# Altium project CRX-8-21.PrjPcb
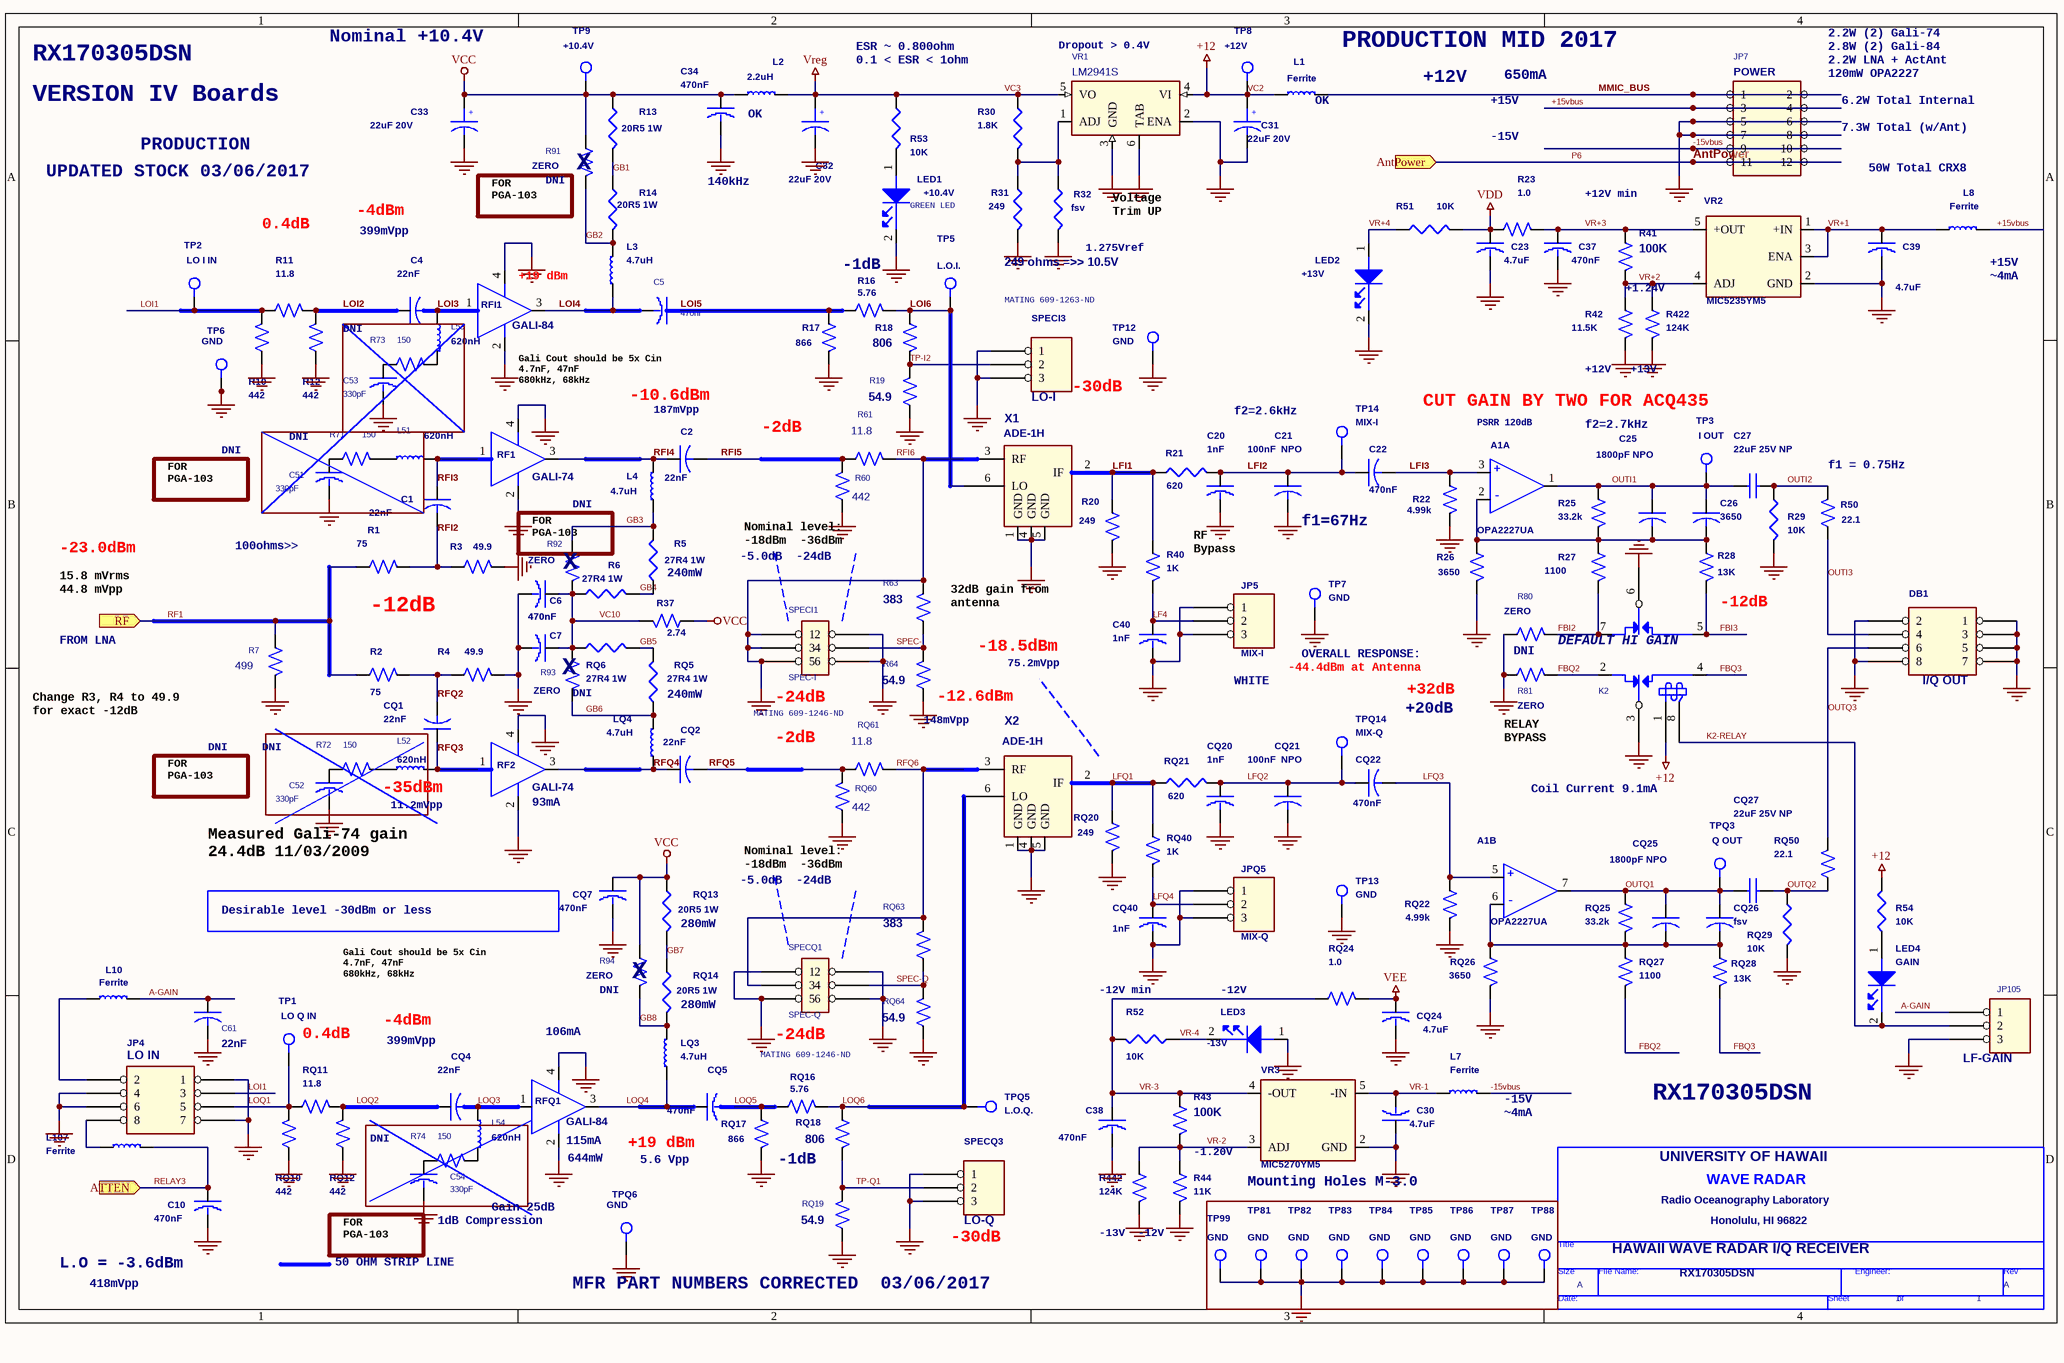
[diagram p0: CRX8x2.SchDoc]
3 sheets, 264 parts. Net scope: flat (ports and power ports of the same name join across sheets).
Board file: CRX-8-21.PcbDoc
Sheets:
  CRX8x2.SchDoc
  LNA.SchDoc
  CHANGE LOG.SchDoc

## Sheet CRX8x2.SchDoc
size 386 x 246 mm; Organization: Altium Limited; Address1: L3, 12a Rodborough Rd; Address2: Frenchs Forest; Address3: NSW; Address4: Australia 2086

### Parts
(Parts that share a designator on the sheet are numbered #1, #2 ... from top to bottom, then left to right.)
*#1  Doc: RX170305DSN  RevCode: A  Title: HAWAII WAVE RADAR I/Q RECEIVER  OrgName: UNIVERSITY OF HAWAII  OrgAddr1: Radio Oceanography Laboratory  OrgAddr3: Honolulu, HI 96822  Page Number: 1  (hidden comment: HWRadar)  (graphical)
A1  OPA2227UA  [DIP8]  (parts A,B of 2)
C1  22nF  [C1206]
C2  22nF  [C1206]
C4  22nF  [C1206]
C5  470nF  [C1206]
C6  470nF  [C1206]
C7  470nF  [C1206]
C10  470nF  [C1206]
C20  1nF  [C1206]
C21  100nF  NPO  [C1206]
C22  470nF  [BFC2_416]
C23  4.7uF  [C1206]
C25  1800pF NPO  [C1206]
C26  3650  [C1206]
C27  22uF 25V NP  [2220]
C30  4.7uF  [C1206]
C31  22uF 20V  [C2917]
C32  22uF 20V  [C2917]
C33  22uF 20V  [C2917]
C34  470nF  [C1206]
C37  470nF  [C1206]
C38  470nF  [C1206]
C39  4.7uF  [C1206]
C40  1nF  [C1206]
C51  330pF  [C1206]
C52  330pF  [C1206]
C53  330pF  [C1206]
C54  330pF  [C1206]
C61  22nF  [C1206]
CQ1  22nF  [C1206]
CQ2  22nF  [C1206]
CQ4  22nF  [C1206]
CQ5  470nF  [C1206]
CQ7  470nF  [C1206]
CQ20  1nF  [C1206]
CQ21  100nF  NPO  [C1206]
CQ22  470nF  [BFC2_416]
CQ24  4.7uF  [C1206]
CQ25  1800pF NPO  [C1206]
CQ26  fsv  [C1206]
CQ27  22uF 25V NP  [2220]
CQ40  1nF  [C1206]
DB1  I/Q OUT  [TSW-4X2M]
JP4  LO IN  [TSW-4X2M]
JP5  MIX-I  [SIP3]
JP7  POWER  [TSW-6X2M]
JP105  LF-GAIN  [SIP3]
JPQ5  MIX-Q  [SIP3]
K2  G6K-2F-RF-S DC12  [RELAY-RF]  (value not drawn)
L1  Ferrite  [L1812]
L2  2.2uH  [L1210]
L3  4.7uH  [L1812]
L4  4.7uH  [L1812]
L7  Ferrite  [L1812]
L8  Ferrite  [L1812]
L10  Ferrite  [L1206]
L51  620nH  [L1008]
L52  620nH  [L1008]
L53  620nH  [L1008]
L54  620nH  [L1008]
L107  Ferrite  [L1206]
LED1  +10.4V  [LED0603]
LED2  +13V  [LED0603]
LED3  -13V  [LED0603]
LED4  GAIN  [LED0603]
LQ3  4.7uH  [L1812]
LQ4  4.7uH  [L1812]
R1  75  [RS400]
R2  75  [RS400]
R3  49.9  [RS400]
R4  49.9  [RS400]
R5  27R4 1W  [R2512]
R6  27R4 1W  [R2512]
R7  499  [RS400]
R10  442  [RS400]
R11  11.8  [RS400]
R12  442  [RS400]
R13  20R5 1W  [R2512]
R14  20R5 1W  [R2512]
R16  5.76  [RS400]
R17  866  [RS400]
R18  806  [RS400]
R19  54.9  [RS400]
R20  249  [RS400]
R21  620  [R1206]
R22  4.99k  [RS400]
R23  1.0  [RS400]
R25  33.2k  [RS400]
R26  3650  [RS400]
R27  1100  [RS400]
R28  13K  [RS400]
R29  10K  [R1206]
R30  1.8K  [R1206]
R31  249  [R1206]
R32  fsv  [R1206]
R37  2.74  [RS400]
R40  1K  [RS400]
R41  100K  [R1206]
R42  11.5K  [R1206]
R43  100K  [R1206]
R44  11K  [R1206]
R50  22.1  [RS400]
R51  10K  [R1206]
R52  10K  [R1206]
R53  10K  [R1206]
R54  10K  [R1206]
R60  442  [RS400]
R61  11.8  [RS400]
R63  383  [RS400]
R64  54.9  [RS400]
R71  150  [R1206]
R72  150  [R1206]
R73  150  [R1206]
R74  150  [R1206]
R80  ZERO  [R1206]
R81  ZERO  [R1206]
R91  ZERO  [R1206]
R92  ZERO  [R1206]
R93  ZERO  [R1206]
R94  ZERO  [R1206]
R422  124K  [R1206]
R442  124K  [R1206]
RF1  GALI-74  [GVA-84]
RF2  GALI-74  [GVA-84]
RFI1  GALI-84  [GVA-84]
RFQ1  GALI-84  [GVA-84]
RQ5  27R4 1W  [R2512]
RQ6  27R4 1W  [R2512]
RQ10  442  [RS400]
RQ11  11.8  [RS400]
RQ12  442  [RS400]
RQ13  20R5 1W  [R2512]
RQ14  20R5 1W  [R2512]
RQ16  5.76  [RS400]
RQ17  866  [RS400]
RQ18  806  [RS400]
RQ19  54.9  [RS400]
RQ20  249  [RS400]
RQ21  620  [R1206]
RQ22  4.99k  [RS400]
RQ24  1.0  [RS400]
RQ25  33.2k  [RS400]
RQ26  3650  [RS400]
RQ27  1100  [RS400]
RQ28  13K  [RS400]
RQ29  10K  [R1206]
RQ40  1K  [RS400]
RQ50  22.1  [RS400]
RQ60  442  [RS400]
RQ61  11.8  [RS400]
RQ63  383  [RS400]
RQ64  54.9  [RS400]
SPECI1  SPEC-I  [TEST-6]
SPECI3  LO-I  [TEST-JUMP]
SPECQ1  SPEC-Q  [TEST-6]
SPECQ3  LO-Q  [TEST-JUMP]
TP1  LO Q IN  [TP]
TP2  LO I IN  [TP]
TP3  I OUT  [TP]
TP5  L.O.I.  [TP]
TP6  GND  [TP]
TP7  GND  [TP]
TP8  +12V  [TP]
TP9  +10.4V  [TP]
TP12  GND  [TP]
TP13  GND  [TP]
TP14  MIX-I  [TP]
TP81  GND  [TP]
TP82  GND  [TP]
TP83  GND  [TP]
TP84  GND  [TP]
TP85  GND  [TP]
TP86  GND  [TP]
TP87  GND  [TP]
TP88  GND  [TP]
TP99  GND  [TP]
TPQ3  Q OUT  [TP]
TPQ5  L.O.Q.  [TP]
TPQ6  GND  [TP]
TPQ14  MIX-Q  [TP]
VR1  LM2941S  [LM78XX-TO220]
VR2  MIC5235YM5  [SOT-23-5]
VR3  MIC5270YM5  [SOT-23-5]
X1  ADE-1H  [CD542]
X2  ADE-1H  [CD542]

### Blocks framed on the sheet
DNI: C53 L53 R73
DNI: C51 L51 R71
-35dBm: C52 L52 R72
DNI: C54 L54 R74
Mounting Holes M-3.0: TP81-TP88 TP99

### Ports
AntPower (in), ATTEN (in), RF (in)

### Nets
LOI1: C6.2 C7.2 C10.2 C20.2 C21.2 C23.2 C30.1 C31.2 C32.2 C33.2 C34.2 C37.2 C38.2 C39.2 C40.2 C51.2 C52.2 C53.2 C54.2 C61.2 CQ7.2 CQ20.2 CQ21.2 CQ24.2 CQ40.2 DB1.1 DB1.2 DB1.3 DB1.5 DB1.7 DB1.8 JP4.1 JP4.3 JP4.4 JP4.5 JP4.6 JP4.7 JP5.1 JP5.3 JP7.5 JP7.6 JP7.7 JP7.8 JP105.3 JPQ5.1 JPQ5.3 K2.3(COMMON2) K2.6(COMMON1) K2.10(GND) K2.11(GND) K2.12(GND) K2.13(GND) K2.14(GND) K2.15(GND) LED1.2(CATHODE) LED2.2(CATHODE) LED3.1(ANODE) R3.2 R4.2 R7.2 R10.1 R10.2 R11.1 R12.1 R17.2 R19.1 R20.2 R22.2 R26.2 R29.2 R31.2 R32.2 R42.2 R44.2 R60.1 R61.2 R63.2 R64.1 R80.1 R81.1 R422.2 R442.2 RF1.2(GND) RF1.4(GND) RF2.2(GND) RF2.4(GND) RFI1.2(GND) RFI1.4(GND) RFQ1.2(GND) RFQ1.4(GND) RQ10.1 RQ10.2 RQ11.1 RQ12.1 RQ17.2 RQ19.1 RQ20.2 RQ22.2 RQ26.2 RQ29.2 RQ60.1 RQ64.1 SPECI1.1 SPECI1.2 SPECI1.3 SPECI1.5 SPECI1.6 SPECI3.1 SPECI3.3 SPECQ1.1 SPECQ1.2 SPECQ1.5 SPECQ1.6 SPECQ3.1 SPECQ3.3 TP1.TP TP2.TP TP6.TP TP7.TP TP12.TP TP13.TP TP81.TP TP82.TP TP83.TP TP84.TP TP85.TP TP86.TP TP87.TP TP88.TP TP99.TP TPQ6.TP VR1.2(ENA) VR1.3(GND) VR1.6(TAB) VR2.2(GND) VR3.2(GND) X1.1(GND) X1.3(RF) X1.4(GND) X1.5(GND) X2.1(GND) X2.4(GND) X2.5(GND)  [also labelled GND, LOQ1, RFI6]
VC2: C31.1 K2.1(COIL1) L1.1 R54.2 TP8.TP VR1.4(VI)  [also labelled +12]
VC3: C32.1 L2.2 R30.1 R53.1 VR1.5(VO)  [also labelled Vreg]
VCC: C33.1 C34.1 CQ7.1 L2.1 R13.1 R37.2 R91.1 R94.1 RQ13.1 TP9.TP
VDD: A1.8(VDD) C23.1 R23.1 R51.2
VEE: A1.4(VEE) CQ24.1 RQ24.2
+15vbus: JP7.3 JP7.4 L8.2
-15vbus: JP7.9 JP7.10 L7.2
A-GAIN: C61.1 JP105.1 L10.2
AntPower: JP7.11 JP7.12 ; port AntPower  [also labelled P6]
FBI2: K2.7(NC2) R27.2 R80.2
FBI3: K2.5(NO2) R28.2
FBQ2: K2.2(NC1) R81.2 RQ27.2
FBQ3: K2.4(NO1) RQ28.2
GB1: R13.2 R14.1
GB2: L3.2 R14.2 R91.2
GB3: L4.2 R5.2 R92.1
GB4: R5.1 R6.2
GB5: RQ5.2 RQ6.2
GB6: LQ4.2 R93.2 RQ5.1
GB7: RQ13.2 RQ14.1
GB8: LQ3.2 R94.2 RQ14.2
K2-RELAY: JP105.2 K2.8(COIL2) LED4.2(CATHODE)
LF4: C40.1 JP5.2 R40.2
LFI1: R20.1 R21.1 R40.1 X1.2(IF)
LFI2: C20.1 C21.1 C22.1 R21.2 TP14.TP
LFI3: A1.3(IN+) C22.2 R22.1
LFQ1: RQ20.1 RQ21.1 RQ40.1 X2.2(IF)
LFQ2: CQ20.1 CQ21.1 CQ22.1 RQ21.2 TPQ14.TP
LFQ3: A1.5(IN+) CQ22.2 RQ22.1
LFQ4: CQ40.1 JPQ5.2 RQ40.2
LOI2: C4.1 R11.2 R12.2
LOI3: C4.2 L53.1 RFI1.1(IN)
LOI4: C5.2 L3.1 RFI1.3(OUT)
LOI5: C5.1 R16.1 R17.1
LOI6: R16.2 R18.1 TP5.TP X1.6(LO)
LOQ2: CQ4.1 RQ11.2 RQ12.2
LOQ3: CQ4.2 L54.1 RFQ1.1(IN)
LOQ4: CQ5.1 LQ3.1 RFQ1.3(OUT)
LOQ5: CQ5.2 RQ16.1 RQ17.1
LOQ6: RQ16.2 RQ18.1 TPQ5.TP X2.6(LO)
MMIC_BUS: JP7.1 JP7.2 L1.2
OUTI1: A1.1(OUT) C25.1 C26.1 C27.1 R25.1 TP3.TP
OUTI2: C27.2 R29.1 R50.1
OUTI3: DB1.4 R50.2
OUTQ1: A1.7(OUT) CQ25.1 CQ26.1 CQ27.1 RQ25.1 TPQ3.TP
OUTQ2: CQ27.2 RQ29.1 RQ50.1
OUTQ3: DB1.6 RQ50.2
RELAY3: C10.1 L107.2 ; port ATTEN
RF1: R1.1 R2.1 R7.1 ; port RF  [project net LNA12]
RFI2: C1.2 R1.2 R3.1
RFI3: C1.1 L51.2 RF1.1(IN)
RFI4: C2.1 L4.1 RF1.3(OUT)
RFI5: C2.2 R60.2 R61.1
RFQ2: CQ1.2 R2.2 R4.1
RFQ3: CQ1.1 L52.2 RF2.1(IN)
RFQ4: CQ2.1 LQ4.1 RF2.3(OUT)
RFQ5: CQ2.2 RQ60.2 RQ61.1
RFQ6: RQ61.2 RQ63.2 SPECQ1.3 X2.3(RF)
SPEC-I: R63.1 R64.2 SPECI1.4
SPEC-Q: RQ63.1 RQ64.2 SPECQ1.4
TP-I2: R18.2 R19.2 SPECI3.2
TP-Q1: RQ18.2 RQ19.2 SPECQ3.2
VC10: C6.1 C7.1 R6.1 R37.1 R92.2 R93.1 RQ6.1
VR+1: C39.1 L8.1 VR2.1(+IN) VR2.3(ENA)
VR+2: R41.2 R42.1 R422.1 VR2.4(ADJ)
VR+3: C37.1 R23.2 R41.1 VR2.5(+OUT)
VR+4: LED2.1(ANODE) R51.1
VR-1: C30.2 L7.1 VR3.5(-IN)
VR-2: R43.2 R44.1 R442.1 VR3.3(ADJ)
VR-3: C38.1 R43.1 R52.2 RQ24.1 VR3.4(-OUT)
VR-4: LED3.2(CATHODE) R52.1
NetA1_2: A1.2(IN-) C25.2 C26.2 R25.2 R26.1 R27.1 R28.1
NetA1_6: A1.6(IN-) CQ25.2 CQ26.2 RQ25.2 RQ26.1 RQ27.1 RQ28.1
NetC51_1: C51.1 R71.1
NetC52_1: C52.1 R72.1
NetC53_1: C53.1 R73.1
NetC54_1: C54.1 R74.1
NetJP4_2: JP4.2 L10.1
NetJP4_8: JP4.8 L107.1
NetL51_1: L51.1 R71.2
NetL52_1: L52.1 R72.2
NetL53_2: L53.2 R73.2
NetL54_2: L54.2 R74.2
NetLED1_1: LED1.1(ANODE) R53.2
NetLED4_1: LED4.1(ANODE) R54.1
NetR30_2: R30.2 R31.1 R32.1 VR1.1(ADJ)

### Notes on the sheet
- RX170305DSN
- Nominal +10.4V
- ESR ~ 0.800ohm
- 0.1 < ESR < 1ohm
- (near VR1) Dropout > 0.4V
- (near L1) PRODUCTION MID 2017
- (near JP7) 2.8W (2) Gali-84
- (near JP7) 2.2W LNA + ActAnt
- 2.2W (2) Gali-74
- VERSION IV Boards
- (near L2) OK
- (near L1) OK
- +12V
- +15V
- 650mA
- (near JP7) 120mW OPA2227
- (near JP7) 6.2W Total Internal
- (near JP7) 7.3W Total (w/Ant)
- UPDATED STOCK 03/06/2017
- PRODUCTION
- (near R91) DNI
- (near R91) X
- 140kHz
- -15V
- +12V min
- 50W Total CRX8
- 0.4dB
- -4dBm
- 399mVpp
- FOR
  PGA-103
- -1dB
- (near LED1) GREEN LED
- 249 ohms =>> 10.5V
- (near R32) 1.275Vref
- Voltage
  Trim UP
- (near L8) +15V
- (near RFI1) +19 dBm
- MATING 609-1263-ND
- +1.24V
- (near L8) ~4mA
- (near RFI1) Gali Cout should be 5x Cin
  4.7nF, 47nF
  680kHz, 68kHz
- -10.6dBm
- -30dB
- CUT GAIN BY TWO FOR ACQ435
- +12V   +13V
- DNI
- 187mVpp
- -2dB
- f2=2.6kHz
- PSRR 120dB
- f2=2.7kHz
- (near R50) f1 = 0.75Hz
- (near C21) f1=67Hz
- 15.8 mVrms
  44.8 mVpp
- -23.0dBm
- 100ohms>>
- (near R92) FOR
  PGA-103
- (near R92) X
- (near R5) 240mW
- -5.0dB  -24dB
- (near R60) Nominal level:
  -18dBm  -36dBm
- RF
  Bypass
- -12dB
- FROM LNA
- (near R1) -12dB
- (near R93) X
- 32dB gain from
  antenna
- -18.5dBm
- 75.2mVpp
- -44.4dBm at Antenna
- (near TP7) OVERALL RESPONSE:
- (near K2) DEFAULT HI GAIN
- (near R7) Change R3, R4 to 49.9
  for exact -12dB
- (near R93) DNI
- (near RQ5) 240mW
- MATING 609-1246-ND
- (near SPECI1) -24dB
- (near R64) 148mVpp
- (near R64) -12.6dBm
- (near JP5) WHITE
- +20dB
- +32dB
- 11.2mVpp
- (near RF2) 93mA
- RELAY
  BYPASS
- Coil Current 9.1mA
- Measured Gali-74 gain
  24.4dB 11/03/2009
- (near RQ60) Nominal level:
  -18dBm  -36dBm
- Desirable level -30dBm or less
- (near RQ13) 280mW
- Gali Cout should be 5x Cin
  4.7nF, 47nF
  680kHz, 68kHz
- (near R94) DNI
- (near R94) X
- (near RQ14) 280mW
- -12V min
- (near LED3) -12V
- (near TP1) 0.4dB
- (near RFQ1) 106mA
- (near SPECQ1) -24dB
- (near RFQ1) 115mA
- +19 dBm
- (near L7) -15V
- ~4mA
- Gain 25dB
- (near RFQ1) 644mW
- 5.6 Vpp
- (near RQ17) -1dB
- -1.20V
- L.O = -3.6dBm
- 50 OHM STRIP LINE
- (near C54) 1dB Compression
- (near SPECQ3) -30dB
- -13V  -12V
- 418mVpp
- MFR PART NUMBERS CORRECTED  03/06/2017

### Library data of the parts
*#1 = HWRadar: Engineer:: <ENG>; OrgAddr2: 2525 Correa Road
A1 = OPAMPx2_3: MFR PART: OPA2227UA/2K5; MFR: Texas Instruments; DK Stock: 296-26245-6-ND
C1 C2 C4 C61 CQ1 CQ2 CQ4 = CAP: MFR: Murata; MFR PART: GRM3195C1H223JA01D; DK Stock: 490-1761-1-ND
C5 CQ5 = C1206: MFR: AVX; MFR PART: 12065C474JAT2A; DK Stock: 478-5784-1-ND
C6 C7 C10 C37 C38 CQ7 = C1206: MFR: TDK; MFR PART: C1632X7R1E224M070AC; DK Stock: 445-14303-2-ND
C20 C40 CQ20 CQ40 = C1206: MFR: AVX; MFR PART: 12061A102FAT2A; DK Stock: 478-3778-1-ND
C21 CQ21 = CAP: MFR: Murata; MFR PART: GRM31C5C1E104JA01L; DK Stock: 490-1767-1-ND
C22 CQ22 = CAP: MFR: Vishay BC; MFR PART: BFC237321474; DK Stock: BC1770-ND
C23 C30 C39 CQ24 = C1206: MFR: TDK; MFR PART: C3225X7R1E475K200AA; DK Stock: 445-1433-1-ND
C25 CQ25 = CAP: MFR: AVX; MFR PART: 12065A182JAT2A; DK Stock: 478-1495-1-ND
C26 CQ26 = CAP: MFR: DNI
C27 CQ27 = CAP NP: MFR: Kemet; MFR PART: C2220X226K3RACTU; DK Stock: 399-5533-1-ND
C31-C33 = CAPACITOR POL: MFR: Kemet; MFR PART: T491D226K020AT; DK Stock: 399-3781-2-ND
C34 = C1206: MFR PART: 12065C474JAT2A; MFR: AVX; DK Stock: 478-5784-1-ND
C51-C54 = C1206: MFR: AVX; MFR PART: 06035A331GAT2A; DK Stock: 478-5776-1-ND
DB1 JP4 = HEADER 4X2: MFR: Samtec; MFR PART: TSW-104-08-S-D-RA; DK Stock: SAM1045-04-ND
JP5 JPQ5 = HEADER 3: MFR: Amphenol; MFR PART: 68000-203HLF; DK Stock: 609-3464-ND
JP7 = HEADER 6X2: MFR: Samtec; MFR PART: TSW-106-08-L-D-RA; DK Stock: SAM1041-06-ND
JP105 = HEADER 3: MFR PART: 68000-203HLF; MFR: Amphenol; DK Stock: 609-3464-ND
K2 = RELAY DPDT_1: MFR: Omron; DK Stock: Z2831-ND
L1 L7 = IND: MFR: Wurth; MFR PART: 742792514; DK Stock: 732-1643-2-ND
L2 = IND: MFR: TDK; MFR PART: NLFV32T-2R2M-EF; DK Stock: 445-15767-1-ND
L3 L4 LQ3 LQ4 = IND: MFR: TE Connectivity; MFR PART: CM453232-4R7KL; DK Stock: CM453232-4R7KLTR-ND
L8 = IND: MFR PART: 742792514; MFR: Wurth; DK Stock: 732-1643-2-ND
L10 L107 = IND: MFR: Wurth; MFR PART: 742792141; DK Stock: 732-4656-1-ND
L51-L54 = IND: MFR: Abracon; MFR PART: AISC-1008-R62G-T; DK Stock: AISC-1008-R62G-TCT-ND
LED1 = LED_2: MFR PART: APT1608ZGCK; MFR: Kingbright; DK Stock: 754-1790-1-ND
LED2 = LED_2: MFR PART: APTD1608SECK/J3-PF; MFR: Kingbright; DK Stock: 754-1801-1-ND
LED3 = LED_2: MFR PART: APTD1608SYCK; MFR: Kingbright; DK Stock: 754-1544-1-ND
LED4 = LED_2: MFR PART: APTD1608SECK; MFR: Kingbright; DK Stock: 754-1860-1-ND
R1 R2 = RES: MFR PART: CRCW120675R0FKEA; MFR: Yageo; DK Stock: 541-75.0FCT-ND
R3 R4 = RES: MFR PART: CRCW120649R9FKEA; MFR: Yageo; DK Stock: 541-49.9FCT-ND
R5 R6 RQ5 RQ6 = RESISTOR: MFR: Vishay Dale; MFR PART: CRCW251227R4FKEG; DK Stock: 541-27.4AFTR-ND
R7 = RES: MFR PART: RC1206FR-07499RL; MFR: Yageo; DK Stock: 311-499FRCT-ND
R10 R12 R60 RQ10 RQ12 RQ60 = RES: MFR PART: RC1206FR-07442RL; MFR: Yageo; DK Stock: 311-442FRCT-ND
R11 R61 RQ61 = RES: MFR PART: RC1206FR-0711R8L; MFR: Yageo; DK Stock: 311-11.8FRCT-ND
R13 R14 RQ13 RQ14 = RESISTOR: MFR: Vishay Dale; MFR PART: CRCW251220R5FKEG; DK Stock: 541-20.5AFCT-ND
R16 = RES: MFR PART: RC1206FR-075R76L; MFR: Yageo; DK Stock: 311-5.76FRCT-ND
R17 RQ17 = RES: MFR PART: RC1206FR-07866RL; MFR: Yageo; DK Stock: 311-866FRCT-ND
R18 RQ18 = RES: MFR PART: RC1206FR-07806RL; MFR: Yageo; DK Stock: 311-806FRCT-ND
R19 R64 RQ19 RQ64 = RES: MFR PART: RC1206FR-0754R9L; MFR: Yageo; DK Stock: 311-54.9FRCT-ND
R20 RQ20 = RES: MFR PART: RC1206FR-07249RL; MFR: Yageo; DK Stock: 311-249FRCT-ND
R21 RQ21 = RESISTOR_Dup1: MFR PART: RC1206FR-07620RL; MFR: Yageo; DK Stock: 311-620FRCT-ND
R22 RQ22 = RES: MFR PART: RC1206FR-074K99L; MFR: Yageo; DK Stock: 311-4.99KFRCT-ND
R23 RQ24 = RES: MFR PART: RC1206FR-07100RL; MFR: Yageo; DK Stock: 311-1.00FRCT-ND
R25 RQ25 = RES: MFR PART: RC1206FR-0733K2L; MFR: Yageo; DK Stock: 311-33.2kFRCT-ND
R26 RQ26 = RES: MFR PART: RC1206FR-073K65L; MFR: Yageo; DK Stock: 311-3.65KFRCT-ND
R27 RQ27 = RES: MFR PART: RC1206FR-071K1L; MFR: Yageo; DK Stock: 311-1.10KFRCT-ND
R28 RQ28 = RES: MFR PART: RC1206FR-0713KL; MFR: Yageo; DK Stock: 311-13.0kFRCT-ND
R29 R51-R54 RQ29 = RESISTOR_Dup1: MFR PART: RC1206FR-0710KL; MFR: Yageo; DK Stock: 311-10.0kFRCT-ND
R30 = RESISTOR_Dup1: MFR PART: RC1206FR-071K8L; MFR: Yageo; DK Stock: 311-1.80kFRCT-ND
R31 = RESISTOR_Dup1: MFR PART: RC1206FR-07249RL; MFR: Yageo; DK Stock: 311-249FRCT-ND
R32 = RESISTOR_Dup1: MFR PART: DNI; DK Stock: OMIT
R37 = RES: MFR PART: RC1206FR-072R74L; MFR: Yageo; DK Stock: 311-2.74FRCT-ND
R40 RQ40 = RES: MFR PART: RC1206FR-071KL; MFR: Yageo; DK Stock: 311-1.00kFRCT-ND
R41 R43 = RES1206_Dup1: MFR PART: RC1206FR-07100KL; MFR: Yageo; DK Stock: 311-100KFRCT-ND
R42 = RES1206_Dup1: MFR PART: RC1206FR-0711K5L; MFR: Yageo; DK Stock: 311-11.5KFRCT-ND
R44 = RES1206_Dup1: MFR PART: RC1206FR-0711KL; MFR: Yageo; DK Stock: 311-11.0KFRCT-ND
R50 RQ50 = RES: MFR PART: RC1206FR-0722R1L; MFR: Yageo; DK Stock: 311-22.1FRCT-ND
R63 RQ63 = RES: MFR PART: RC1206FR-07383RL; MFR: Yageo; DK Stock: 311-383FRCT-ND
R71-R74 = R1206: MFR PART: RC0603FR-07150RL; MFR: Yageo; DK Stock: 311-150HRCT-ND
R80 R81 R91-R94 = R1206: MFR PART: RC1206JR-070RL; MFR: Yageo; DK Stock: 311-0.0ERCT-ND
R422 R442 = RES1206_Dup1: MFR PART: RC1206FR-07124KL; MFR: Yageo; DK Stock: 311-124KFRCT-ND
RF1 RF2 = GVA-84: MFR: MiniCircuits; MFR PART: GALI-74+
RFI1 RFQ1 = GVA-84: MFR: MiniCircuits; MFR PART: GALI-84+
RQ11 = RES: MFR: Yageo; MFR PART: RC1206FR-0711R8L; DK Stock: 311-11.8FRCT-ND
RQ16 = RES: MFR: Yageo; MFR PART: RC1206FR-075R76L; DK Stock: 311-5.76FRCT-ND
SPECI1 SPECQ1 = HEADER 3X2_0: MFR: Amphenol; MFR PART: 76385-303LF; DK Stock: 609-1331-ND
SPECI3 SPECQ3 = HEADER 3: MFR: Amphenol; MFR PART: 76384-303LF; DK Stock: 609-1305-ND
TP1-TP3 TP5-TP9 TP12-TP14 TPQ3 TPQ5 TPQ6 TPQ14 = TP_3: DK Stock: DNI
TP81-TP88 TP99 = TP_5: MFR: DNI
VR1 = LM7805_0: MFR PART: LM2941SX/NOPB; MFR: Texas Instruments; DK Stock: LM2941SX/NOPBCT-ND
VR2 = MIC5235: MFR: Microhip Technology; MFR PART: MIC5235YM5-TR; DK Stock: 576-1284-1-ND
VR3 = MIC5270: MFR: Microhip Technology; MFR PART: MIC5270YM5-TR; DK Stock: 576-1295-1-ND
X1 X2 = MIXER_1: MFR PART: ADE-1H+; MFR: MiniCircuits

## Sheet LNA.SchDoc
size A3; Organization: Altium Limited; Address1: L3, 12a Rodborough Rd; Address2: Frenchs Forest; Address3: NSW; Address4: Australia 2086
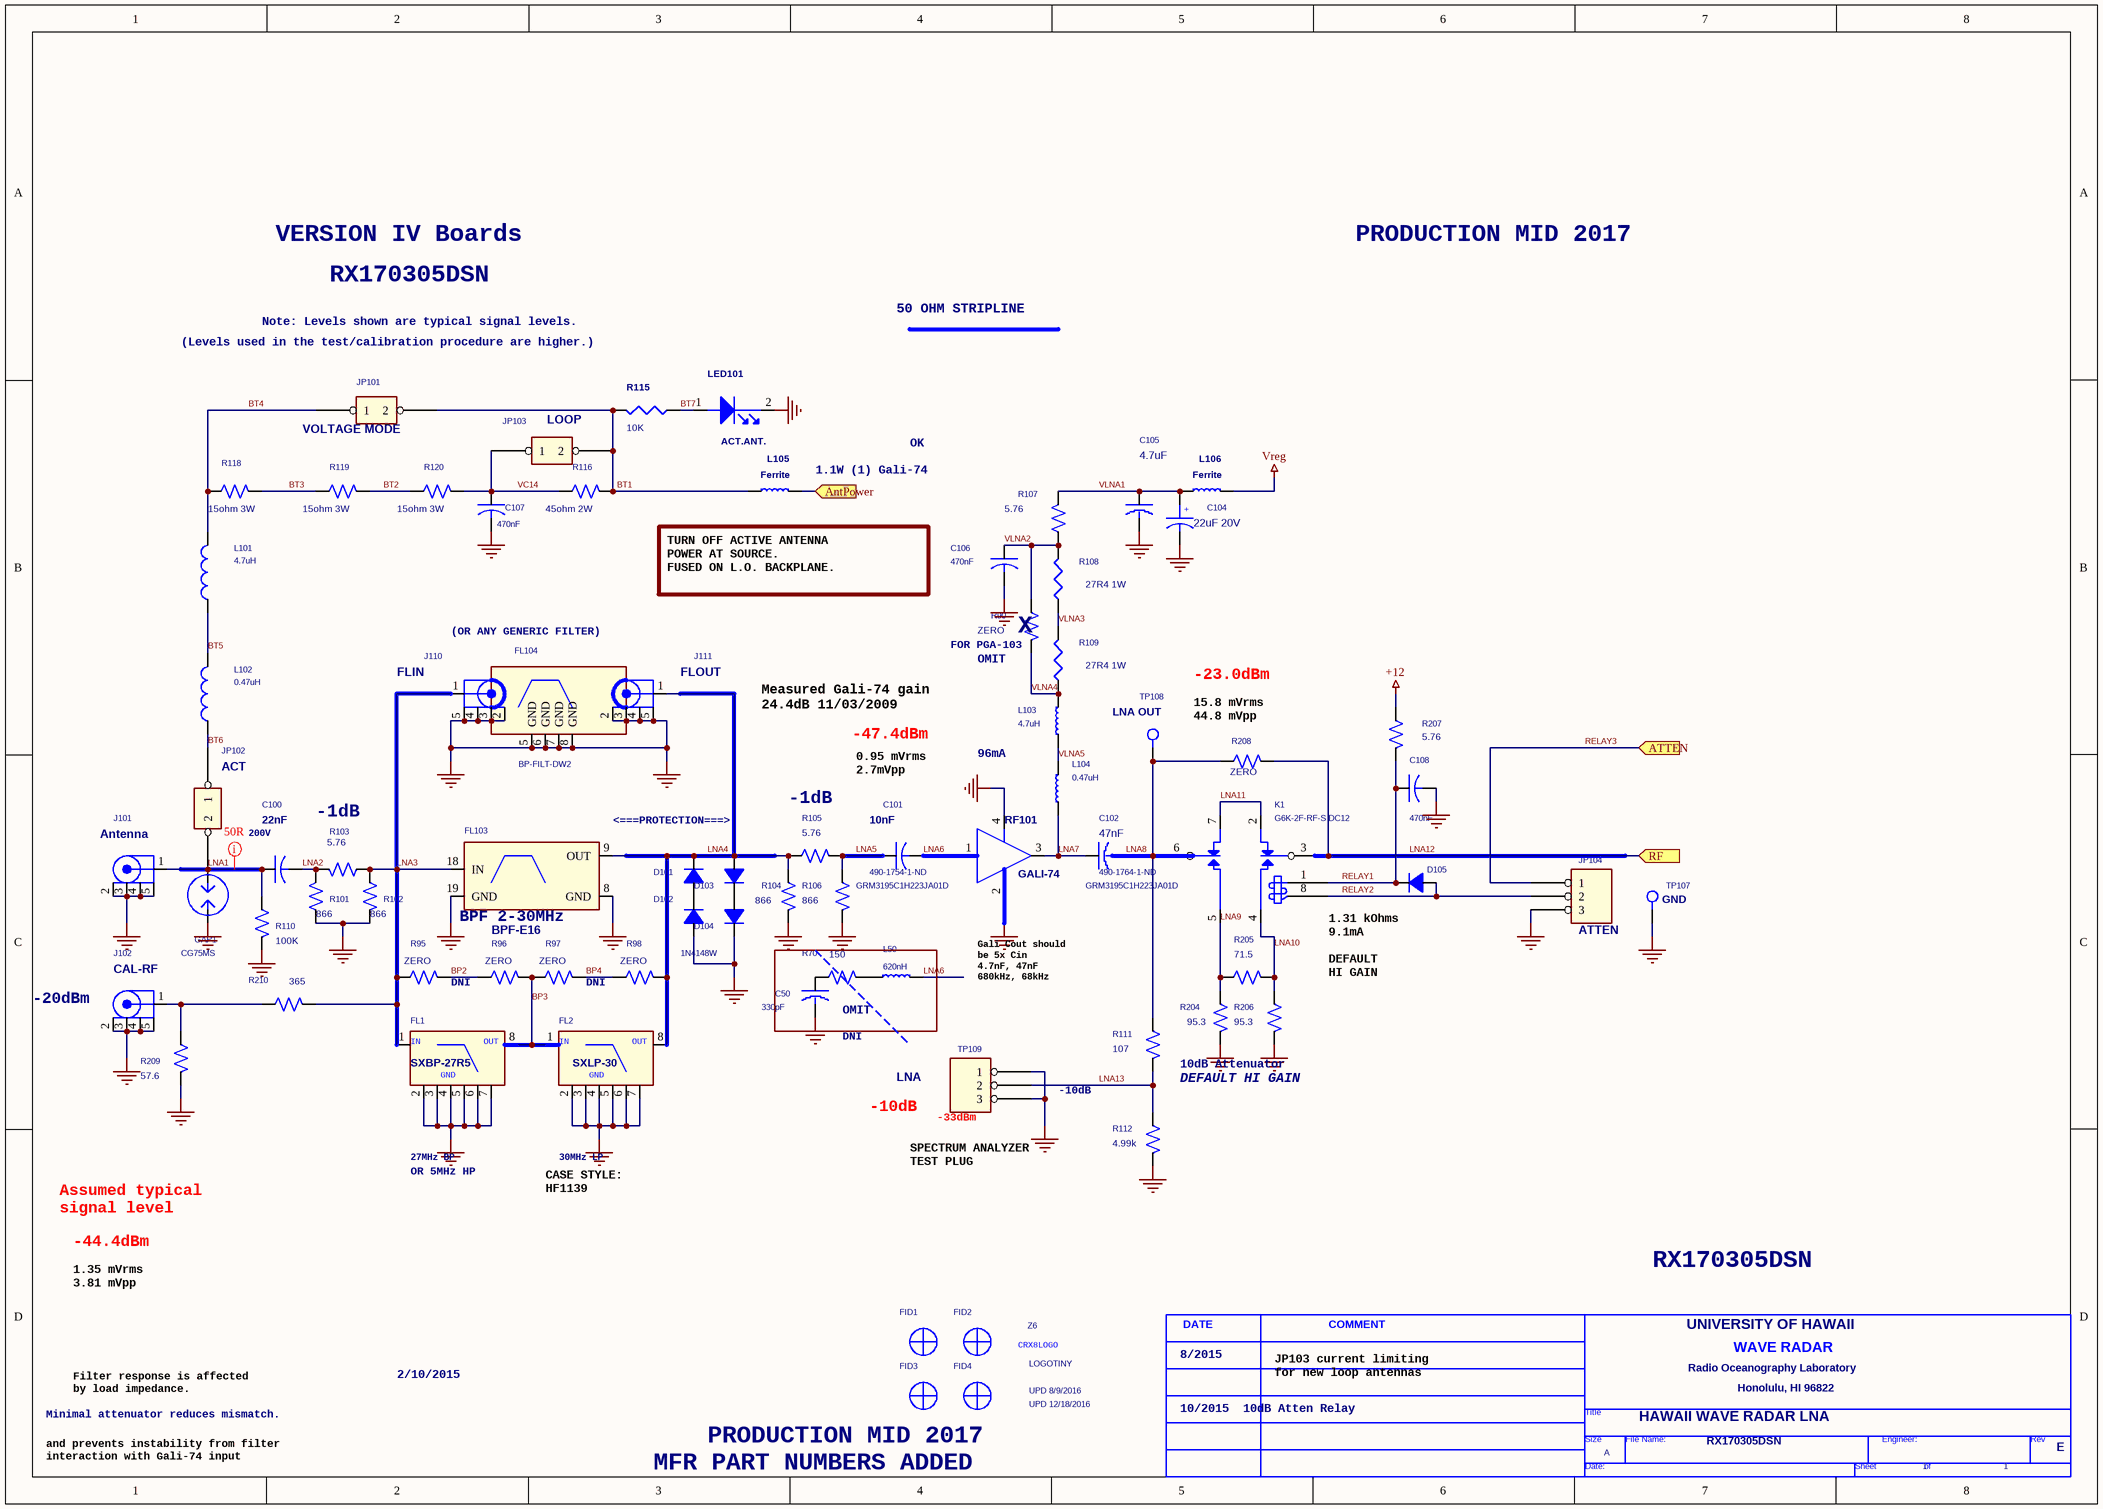
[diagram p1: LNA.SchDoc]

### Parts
(Parts that share a designator on the sheet are numbered #1, #2 ... from top to bottom, then left to right.)
*#2  DCB  (value not drawn)  (graphical)
*#3  Doc: RX170305DSN  RevCode: E  Title: HAWAII WAVE RADAR LNA  OrgName: UNIVERSITY OF HAWAII  OrgAddr1: Radio Oceanography Laboratory  OrgAddr3: Honolulu, HI 96822  Page Size: A  Page Number: 1  (hidden comment: HWRadar)  (graphical)
C50  330pF  [C1206]
C100  22nF  [C1206]
C101  10nF  MFR PART: GRM3195C1H223JA01D  DK Stock: 490-1754-1-ND  [C1206]
C102  47nF  MFR PART: GRM3195C1H223JA01D  DK Stock: 490-1764-1-ND  [C1206]
C104  22uF 20V  [C2917]
C105  4.7uF  [C1206]
C106  470nF  [C0612]
C107  470nF  [C0612]
C108  470nF  [C0612]
D101  1N4148W  [SOD123]  (value not drawn)
D102  1N4148W  [SOD123]  (value not drawn)
D103  1N4148W  [SOD123]  (value not drawn)
D104  1N4148W  [SOD123]
D105  1N4148W  [SOD123]  (value not drawn)
FID1  FIDUCIAL  [FIDUCIAL]  (value not drawn)
FID2  FIDUCIAL  [FIDUCIAL]  (value not drawn)
FID3  FIDUCIAL  [FIDUCIAL]  (value not drawn)
FID4  FIDUCIAL  [FIDUCIAL]  (value not drawn)
FL1  SXBP-27R5  [HF1149]
FL2  SXLP-30  [HF1149]
FL103  BPF-E16  [HR1176]
FL104  BP-FILT-DW2  [BP-FILTER-DW]
GAP1  CG75MS  [SG-1]
J101  Antenna  [SMA]
J102  CAL-RF  [SMA]
J110  FLIN  [SMA]
J111  FLOUT  [SMA]
JP101  VOLTAGE MODE  [SIP2]
JP102  ACT  [SIP2]
JP103  LOOP  [SIP2]
JP104  ATTEN  [SIP3]
K1  G6K-2F-RF-S DC12  [RELAY-RF]
L50  620nH  [L1008]
L101  4.7uH  [L1812]
L102  0.47uH  [L1210]
L103  4.7uH  [L1812]
L104  0.47uH  [L1210]
L105  Ferrite  [L1812]
L106  Ferrite  [L1812]
LED101  ACT.ANT.  [LED0603]
R70  150  [R1206]
R90  ZERO  [R1206]
R95  ZERO  [R1206]
R96  ZERO  [R1206]
R97  ZERO  [R1206]
R98  ZERO  [R1206]
R101  866  [RS400]
R102  866  [RS400]
R103  5.76  [RS400]
R104  866  [RS400]
R105  5.76  [RS400]
R106  866  [RS400]
R107  5.76  [RS400]
R108  27R4 1W  [R2512]
R109  27R4 1W  [R2512]
R110  100K  [RS400]
R111  107  [RS400]
R112  4.99k  [RS400]
R115  10K  [R1206]
R116  45ohm 2W  [R1206]
R118  15ohm 3W  [R1206]
R119  15ohm 3W  [R1206]
R120  15ohm 3W  [R1206]
R204  95.3  [RS400]
R205  71.5  [RS400]
R206  95.3  [RS400]
R207  5.76  [R1206]
R208  ZERO  [R1206]
R209  57.6  [R1206]
R210  365  [R1206]
RF101  GALI-74  [GVA-84]
TP107  GND  [TP]
TP108  LNA OUT  [TP]
TP109  LNA  [TEST-JUMP]
Z6  LOGOTINY  MFR PART: UPD 12/18/2016  MFR: UPD 8/9/2016  [CRX8TINY]

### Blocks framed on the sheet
OMIT: C50 L50 R70

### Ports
AntPower (in), ATTEN (in), RF (in)

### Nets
+12: R207.1  [project net VC2]
GND: C50.2 C104.2 C105.2 C106.2 C107.2 C108.2 D102.ANOD D104.CATH FL1.2(GND) FL1.3(GND) FL1.4(GND) FL1.5(GND) FL1.6(GND) FL1.7(GND) FL2.2(GND) FL2.3(GND) FL2.4(GND) FL2.5(GND) FL2.6(GND) FL2.7(GND) FL103.1(GND) FL103.2(GND) FL103.3(GND) FL103.4(GND) FL103.5(GND) FL103.6(GND) FL103.7(GND) FL103.8(GND) FL103.10(GND) FL103.11(GND) FL103.12(GND) FL103.13(GND) FL103.14(GND) FL103.15(GND) FL103.16(GND) FL103.17(GND) FL103.19(GND) FL103.20(GND) FL104.5(GND) FL104.6(GND) FL104.7(GND) FL104.8(GND) GAP1.2 J101.2(SHIELD) J101.3(SHIELD) J101.4(SHIELD) J101.5(SHIELD) J102.2(SHIELD) J102.3(SHIELD) J102.4(SHIELD) J102.5(SHIELD) J110.2(SHIELD) J110.3(SHIELD) J110.4(SHIELD) J110.5(SHIELD) J111.2(SHIELD) J111.3(SHIELD) J111.4(SHIELD) J111.5(SHIELD) JP104.3 K1.10(GND) K1.11(GND) K1.12(GND) K1.13(GND) K1.14(GND) K1.15(GND) LED101.2(CATHODE) R101.2 R102.1 R104.2 R106.2 R110.2 R112.2 R204.2 R206.2 R209.2 RF101.2(GND) RF101.4(GND) TP107.TP TP109.1 TP109.3  [project net LOI1]
Vreg: L106.2  [project net VC3]
AntPower: L105.2 ; port AntPower
BP2: R95.2 R96.1
BP3: FL1.8(OUT) FL2.1(IN) R96.2 R97.1
BP4: R97.2 R98.1
BT1: JP101.2 JP103.2 L105.1 R115.2 R116.2
BT2: R119.2 R120.1
BT3: R118.2 R119.1
BT4: JP101.1 L101.1 R118.1
BT5: L101.2 L102.1
BT6: JP102.1 L102.2
BT7: LED101.1(ANODE) R115.1
LNA1: C100.1 GAP1.1 J101.1(CENTER) JP102.2 R110.1
LNA2: C100.2 R101.1 R103.1
LNA3: FL1.1(IN) FL103.18(IN) J110.1(CENTER) R95.1 R102.2 R103.2 R210.2
LNA4: D101.CATH D103.ANOD FL2.8(OUT) FL103.9(OUT) J111.1(CENTER) R98.2 R104.1 R105.1
LNA5: C101.1 R105.2 R106.1
LNA6: C101.2 L50.2 RF101.1(IN)
LNA7: C102.1 L104.1 RF101.3(OUT)
LNA8: C102.2 K1.6(COMMON1) R111.1 R208.1 TP108.TP
LNA9: K1.5(NO2) R204.1 R205.1
LNA10: K1.4(NO1) R205.2 R206.1
LNA11: K1.2(NC1) K1.7(NC2)
LNA12: K1.3(COMMON2) R208.2 ; port RF
LNA13: R111.2 R112.1 TP109.2
RELAY1: C108.1 D105.CATH K1.1(COIL1) R207.2
RELAY2: D105.ANOD JP104.2 K1.8(COIL2)
RELAY3: JP104.1 ; port ATTEN
VC14: C107.1 JP103.1 R116.1 R120.2
VLNA1: C104.1 C105.1 L106.1 R107.1
VLNA2: C106.1 R90.1 R107.2 R108.2
VLNA3: R108.1 R109.2
VLNA4: L103.2 R90.2 R109.1
VLNA5: L103.1 L104.2
NetC50_1: C50.1 R70.1
NetD101_ANOD: D101.ANOD D102.CATH
NetD103_CATH: D103.CATH D104.ANOD
NetJ102_1: J102.1(CENTER) R209.1 R210.1
NetL50_1: L50.1 R70.2

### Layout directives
mark named 50R: LNA1

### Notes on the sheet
- VERSION IV Boards
- PRODUCTION MID 2017
- RX170305DSN
- 50 OHM STRIPLINE
- (Levels used in the test/calibration procedure are higher.)
- Note: Levels shown are typical signal levels.
- OK
- (near L105) 1.1W (1) Gali-74
- (near L105) TURN OFF ACTIVE ANTENNA
  POWER AT SOURCE.
  FUSED ON L.O. BACKPLANE.
- (OR ANY GENERIC FILTER)
- (near R90) FOR PGA-103
- (near R90) X
- Measured Gali-74 gain
  24.4dB 11/03/2009
- (near R90) OMIT
- -23.0dBm
- -47.4dBm
- 0.95 mVrms
  2.7mVpp
- 96mA
- 15.8 mVrms
  44.8 mVpp
- 200V
- -1dB
- <===PROTECTION===>
- (near FL103) BPF 2-30MHz
- DNI
- 1.31 kOhms
  9.1mA
- DEFAULT
  HI GAIN
- (near J102) -20dBm
- Gali Cout should
  be 5x Cin
  4.7nF, 47nF
  680kHz, 68kHz
- -10dB
- (near TP109) -33dBm
- 10dB Attenuator
- DEFAULT HI GAIN
- 27MHz BP
- OR 5MHz HP
- 30MHz LP
- SPECTRUM ANALYZER
  TEST PLUG
- Assumed typical
  signal level
- -44.4dBm
- CASE STYLE:
  HF1139
- 1.35 mVrms
  3.81 mVpp
- 2/10/2015
- (near *#2) 8/2015
- JP103 current limiting
  for new loop antennas
- Minimal attenuator reduces mismatch.
- Filter response is affected
  by load impedance.
- 10/2015  10dB Atten Relay
- and prevents instability from filter
  interaction with Gali-74 input
- MFR PART NUMBERS ADDED

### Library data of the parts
*#3 = HWRadar: as *#1 on sheet CRX8x2
C50 = C1206: as C51 on sheet CRX8x2
C100 = CAP: as C1 on sheet CRX8x2
C101 = CAP: MFR: Murata
C102 = C1206: MFR: Murata
C104 = CAPACITOR POL: as C31 on sheet CRX8x2
C105 = C1206: as C23 on sheet CRX8x2
C106-C108 = CAP: MFR: TDK; MFR PART: C1632X7R1E224M070AC; DK Stock: 445-14303-2-ND
D101-D105 = DIODE2: MFR: Micro Commercial; MFR PART: 1N4148W-TP; DK Stock: 1N4148WTPMSCT-ND
FL1 = LP FILTER_1: MFR: MCI; MFR PART: SXBP-27R5+; DK Stock: MiniCircuits
FL2 = LP FILTER_1: MFR: MCI; MFR PART: SXLP-30+; DK Stock: MiniCircuits
FL103 = BPF-E16: MFR: MCI; MFR PART: BPF-E16+; DK Stock: MiniCircuits
FL104 = BP-FILTER-DW_1
GAP1 = SPARK GAP: MFR: Littlefuse; MFR PART: CG75MS+; DK Stock: F2723CT-ND
J101 J102 = SMA-4G: MFR: Cinch Connectivity Solutions Johnson; MFR PART: 133-3701-211; DK Stock: J539-ND
J110 J111 = SMA-4G: MFR PART: 133-3701-211; MFR: Cinch Connectivity Solutions Johnson; DK Stock: J539-ND
JP101-JP103 = HEADER 2_0: MFR: Amphenol; MFR PART: 68000-202HLF; DK Stock: 609-3502-ND
JP104 = HEADER 3: as JP105 on sheet CRX8x2
K1 = RELAY DPDT_1: MFR: Omron; DK Stock: Z2831-ND
L50 = IND: as L51 on sheet CRX8x2
L101 = INDUCTOR: MFR PART: NLFV32T-4R7M-EF; MFR: TDK; DK Stock: 445-15773-1-ND
L102 = INDUCTOR: MFR PART: B82422A3471K100; MFR: EPCOS; DK Stock: 495-1718-1-ND
L103 = IND: MFR: TE Connectivity; MFR PART: CM453232-4R7KL; DK Stock: A115984CT-ND
L104 = IND: MFR PART: B82422A3471K100; MFR: EPCOS; DK Stock: 495-1718-1-ND
L105 L106 = IND: as L1 on sheet CRX8x2
LED101 = LED_2: MFR PART: APT1608QBC/D; MFR: Kingbright; DK Stock: 754-1434-1-ND
R70 = R1206: as R71 on sheet CRX8x2
R90 R95-R98 = R1206: as R80 on sheet CRX8x2
R101 R102 R104 R106 = RES: MFR: Yageo; MFR PART: RC1206FR-07866RL; DK Stock: 311-866FRCT-ND
R103 R105 R107 = RES: as R16 on sheet CRX8x2
R108 R109 = RESISTOR: MFR PART: CRCW251227R4FKEG; MFR: Vishay Dale; DK Stock: 541-27.4AFTR-ND
R110 = RES: MFR PART: RC1206FR-07100KL; MFR: Yageo; DK Stock: 311-100KFRCT-ND
R111 = RES: MFR PART: RC1206FR-07150RL; MFR: Yageo; DK Stock: 311-107FRCT-ND
R112 = RES: MFR PART: RC1206FR-0710KL; MFR: Yageo; DK Stock: 311-4.99KFRCT-ND
R115 = RESISTOR_Dup1: as R29 on sheet CRX8x2
R116 = R1206: MFR PART: 352130RFT; MFR: TE Connectivity AMP; DK Stock: A121259CT-ND
R118-R120 = R1206: MFR PART: 352110RFT; MFR: TE Connectivity AMP; DK Stock: A121147CT-ND
R204 R206 = RES: MFR PART: RC1206FR-0795R3L; MFR: Yageo; DK Stock: 311-95.3FRCT-ND
R205 = RES: MFR PART: RC1206FR-0771R5L; MFR: Yageo; DK Stock: 311-71.5FRCT-ND
R207 = RES1206_Dup1: MFR PART: RC1206FR-075R76L; MFR: Yageo; DK Stock: 311-5.76FRCT-ND
R208 = RES1206: MFR PART: RC1206JR-070RL; MFR: Yageo; DK Stock: 311-0.0ERCT-ND
R209 = RES1206: MFR PART: RC1206FR-0757R6L; MFR: Yageo; DK Stock: 311-57.6FRCT-ND
R210 = RES1206: MFR PART: RC1206FR-07365RL; MFR: Yageo; DK Stock: 311-365FRCT-ND
RF101 = GVA-84: MFR: MiniCircuits; MFR PART: Gali-74+
TP107 TP108 = TP_5: DK Stock: n/s
TP109 = HEADER 3: MFR PART: 76384-303LF; MFR: Amphenol; DK Stock: 609-1305-ND
Z6 = CRX8LOGO

## Sheet CHANGE LOG.SchDoc
size 246 x 182 mm; Organization: Altium Limited; Address1: L3, 12a Rodborough Rd; Address2: Frenchs Forest; Address3: NSW; Address4: Australia 2086
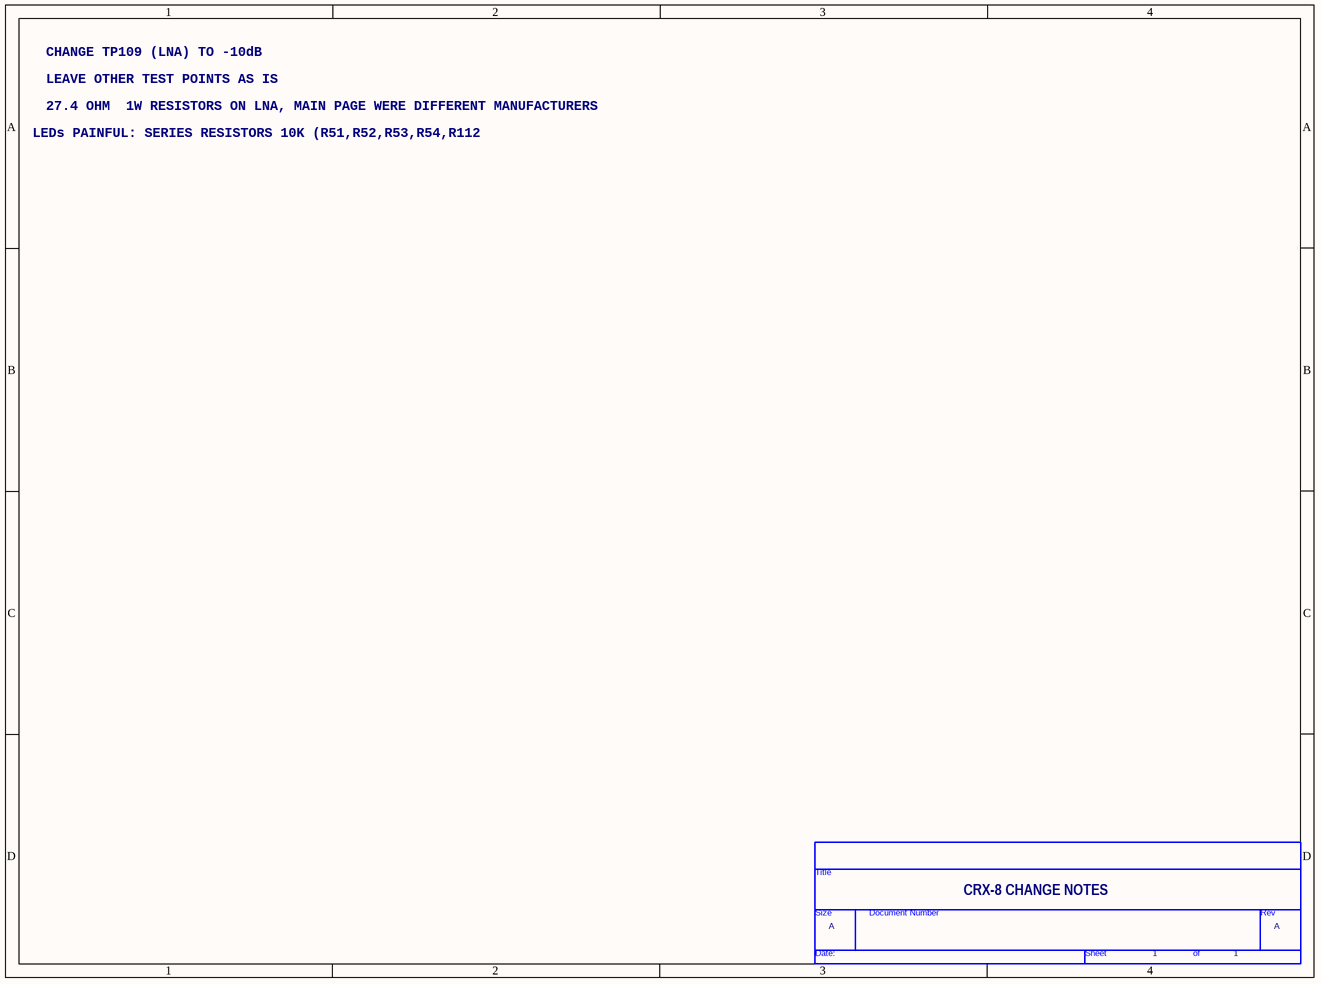
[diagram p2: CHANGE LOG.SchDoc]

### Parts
(Parts that share a designator on the sheet are numbered #1, #2 ... from top to bottom, then left to right.)
*#4  Page Count: 1  Page Size: A  Title: CRX-8 CHANGE NOTES  (hidden comment: TitleBlock0)  (graphical)

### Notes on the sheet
- CHANGE TP109 (LNA) TO -10dB
- LEAVE OTHER TEST POINTS AS IS
- 27.4 OHM  1W RESISTORS ON LNA, MAIN PAGE WERE DIFFERENT MANUFACTURERS
- LEDs PAINFUL: SERIES RESISTORS 10K (R51,R52,R53,R54,R112

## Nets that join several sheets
LOI1: CRX8x2 (143 pins), LNA (81 pins)
VC2: CRX8x2 (6 pins), LNA (R207.1)
VC3: CRX8x2 (5 pins), LNA (L106.2)
AntPower: CRX8x2 (JP7.11 JP7.12), LNA (L105.2)
LNA12: CRX8x2 (R1.1 R2.1 R7.1), LNA (K1.3 R208.2)
RELAY3: CRX8x2 (C10.1 L107.2), LNA (JP104.1)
